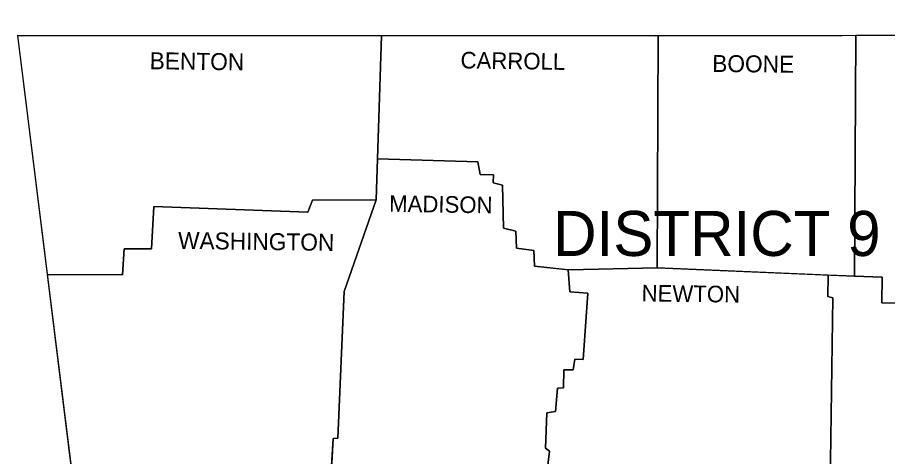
# Model space of a CAD drawing. Extents: x -28335 to 1228743, y -22428 to 152440.
# Drawn here: x 24268 to 29265, y 15008 to 17527 of the extents above; entities that cross this region are included whole.
import ezdxf

# ---------------------------------------------------------------- set-up
doc = ezdxf.new("R2010")
doc.units = 0
doc.layers.add('16', color=7, linetype='Continuous')
doc.layers.add('8', color=7, linetype='Continuous')

msp = doc.modelspace()

# ---------------------------------------------------------------- linework, layer by layer
at = {"layer": '16'}
for p, q in [((26359.6, 17421.4), (24268.3, 17422.7)), ((24268.3, 17422.7), (24439, 16052.3)), ((26359.6, 17421.4), (26335.5, 16716.6)), ((27931.3, 17420.4), (26359.6, 17421.4)), ((27947.2, 17420.5), (27931.3, 17420.4)), ((27947.2, 17420.5), (27942.6, 16090.7)), ((29082.2, 17422.9), (27947.2, 17420.5)), ((29075.2, 16043), (29082.2, 17422.9)), ((29082.2, 17422.9), (29075.2, 16043)), ((30078.9, 17425), (29082.2, 17422.9)), ((26335.5, 16716.6), (26327.5, 16480.3)), ((26911.9, 16697.8), (26335.5, 16716.6)), ((26925.5, 16625.3), (26911.9, 16697.8)), ((27054.6, 16564.2), (27000.3, 16577.8)), ((27059.2, 16317.2), (27054.6, 16564.2)), ((25052.1, 16441.8), (25038.5, 16199.5)), ((25935.6, 16410.1), (25052.1, 16441.8)), ((25962.7, 16478.1), (25935.6, 16410.1)), ((26327.5, 16480.3), (25962.7, 16478.1)), ((27129.4, 16301.4), (27059.2, 16317.2)), ((25038.5, 16199.5), (24882.2, 16199.5)), ((27430.3, 16079.9), (27238.1, 16099.8)), ((27942.6, 16090.7), (27435.2, 16079.4)), ((27942.6, 16090.7), (29075.2, 16043)), ((28923.6, 16049.4), (27942.6, 16090.7)), ((24439, 16052.3), (24587.9, 14856.6)), ((27435.2, 16079.4), (27430.3, 16079.9)), ((27308.3, 15259.4), (27358.2, 15266.2)), ((26067.3, 14865.5), (26080.5, 15112.1)), ((26080.5, 15112.1), (26107.7, 15114.4))]:
    msp.add_line(p, q, dxfattribs=at)
for points in [[(26327.5, 16480.3), (26335.5, 16716.6), (26359.6, 17421.4)], [(26335.5, 16716.6), (26911.9, 16697.8), (26925.5, 16625.3), (27002.5, 16623.1), (27000.3, 16577.8), (27054.6, 16564.2), (27059.2, 16317.2), (27129.4, 16301.4), (27133.9, 16204), (27233.6, 16190.4), (27238.1, 16099.8), (27435.2, 16079.4), (27942.6, 16090.7), (27947.2, 17420.5)], [(27000.3, 16577.8), (27002.5, 16623.1), (26925.5, 16625.3)], [(24439, 16052.3), (24870.9, 16049.9), (24882.2, 16199.5), (25038.5, 16199.5), (25052.1, 16441.8), (25935.6, 16410.1), (25962.7, 16478.1), (26327.5, 16480.3)], [(26327.5, 16480.3), (26144, 15954.8), (26107.7, 15114.4), (26080.5, 15112.1), (26067.3, 14865.5), (26066.9, 14858.4), (26200.6, 14847.1), (26221, 14867.5), (26825.8, 14856.1)], [(26107.7, 15114.4), (26144, 15954.8), (26327.5, 16480.3)], [(27238.1, 16099.8), (27233.6, 16190.4), (27133.9, 16204), (27129.4, 16301.4)], [(24882.2, 16199.5), (24870.9, 16049.9), (24439, 16052.3)], [(27430.3, 16079.9), (27439.7, 15952.5), (27543.9, 15945.7), (27516.7, 15565.2), (27469.2, 15567.5), (27460.1, 15506.3), (27405.7, 15506.3), (27403.5, 15402.1), (27369.5, 15399.8), (27358.2, 15266.2), (27308.3, 15259.4), (27301.5, 15055.5), (27324.2, 15039.6), (27301.5, 14847.1)], [(27516.7, 15565.2), (27543.9, 15945.7), (27439.7, 15952.5), (27430.3, 16079.9)], [(28932.4, 14713.9), (28950.7, 15918.6), (28921.2, 15925.4), (28923.6, 16049.4)], [(28923.6, 16049.4), (28921.2, 15925.4), (28950.7, 15918.6), (28932.4, 14713.9)], [(30421.8, 15880), (29231.6, 15889.1), (29233.8, 16036.4), (29075.2, 16043), (28923.6, 16049.4)], [(29075.2, 16043), (29233.8, 16036.4), (29231.6, 15889.1), (30421.8, 15880)], [(27460.1, 15506.3), (27469.2, 15567.5), (27516.7, 15565.2)], [(27358.2, 15266.2), (27369.5, 15399.8), (27403.5, 15402.1), (27405.7, 15506.3), (27460.1, 15506.3)], [(27301.5, 14847.1), (27324.2, 15039.6), (27301.5, 15055.5), (27308.3, 15259.4)]]:
    msp.add_lwpolyline(points, dxfattribs=at)
at = {"layer": '8'}
for points in [[(24268.3, 17422.7), (27931.3, 17420.4), (31145.8, 17427.2), (34937.9, 17486.1), (36695.7, 17526.9)], [(24268.3, 17422.7), (24737.2, 13657.8), (24533.3, 7512.2)], [(26359.6, 17421.4), (26327.5, 16480.3)], [(26335.5, 16716.6), (26911.9, 16697.8), (26925.5, 16625.3), (27002.5, 16623.1), (27000.3, 16577.8), (27054.6, 16564.2), (27059.2, 16317.2), (27129.4, 16301.4), (27133.9, 16204), (27233.6, 16190.4), (27238.1, 16099.8), (27435.2, 16079.4), (27942.6, 16090.7), (27947.2, 17420.5)], [(29082.2, 17422.9), (29075.2, 16043)], [(24439, 16052.3), (24870.9, 16049.9), (24882.2, 16199.5), (25038.5, 16199.5), (25052.1, 16441.8), (25935.6, 16410.1), (25962.7, 16478.1), (26327.5, 16480.3), (26144, 15954.8), (26107.7, 15114.4), (26080.5, 15112.1), (26066.9, 14858.4), (26200.6, 14847.1), (26221, 14867.5), (27301.5, 14847.1), (27312.9, 14727)], [(27942.6, 16090.7), (29233.8, 16036.4), (29231.6, 15889.1), (30421.8, 15880)], [(27430.3, 16079.9), (27439.7, 15952.5), (27543.9, 15945.7), (27516.7, 15565.2), (27469.2, 15567.5), (27460.1, 15506.3), (27405.7, 15506.3), (27403.5, 15402.1), (27369.5, 15399.8), (27358.2, 15266.2), (27308.3, 15259.4), (27301.5, 15055.5), (27324.2, 15039.6), (27301.5, 14847.1)], [(28923.6, 16049.4), (28921.2, 15925.4), (28950.7, 15918.6), (28932.4, 14713.9)]]:
    msp.add_lwpolyline(points, dxfattribs=at)

# ---------------------------------------------------------------- texts
for s, height, rotation, p in [('BENTON', 97.42, 359.2527, (25027.2, 17230.1)), ('CARROLL', 95.15, 359.1481, (26812.2, 17234.7)), ('BOONE', 97.42, 359.4001, (28257.5, 17214.3)), ('MADISON', 95.15, 359.0906, (26402.2, 16412.4)), ('WASHINGTON', 97.4, 359.232, (25190.3, 16199.5)), ('NEWTON', 95.15, 359.2717, (27852, 15898.2))]:
    msp.add_text(s, height=height, rotation=rotation, dxfattribs=at).set_placement(p)
msp.add_text('DISTRICT 9', height=258.24, dxfattribs=at).set_placement((27344.6, 16158.7))

doc.saveas('drawing.dxf')
